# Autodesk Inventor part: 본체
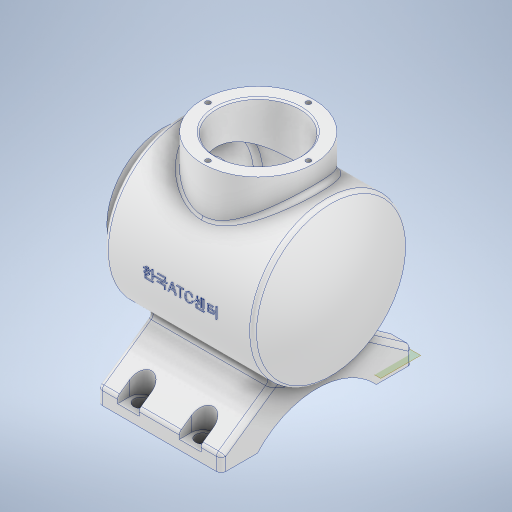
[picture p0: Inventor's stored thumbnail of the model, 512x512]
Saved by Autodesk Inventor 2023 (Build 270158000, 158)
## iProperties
Created: 2023-12
Part Number: 본체
Material: 알루미늄 6061
Document SubType Name: Modeling
Designer: asung
Mass: 1296.69 g
Surface Area: 1060.45 cm^2
Volume: 480.256 cm^3
Density: 2.7 g/cm^3
Appearance: 알루미늄 - 평지
Author: asung
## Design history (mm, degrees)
sketch "스케치1"
  geometry: L1 (60, 0)-(-60, 0); L2 (-60, 0)-(-60, 36); L3 (-60, 36)-(-48, 36); L4 (-48, 36)-(-48, 50); L5 (-48, 50)-(48.336, 50); L6 (-41, 43)-(43.887, 43); L7 (-41, 27)-(-41, 43); L8 (-60, 0)-(-60, 27); L9 (-60, 27)-(-41, 27); A1 r 113 centre (-53, 0) between (60, 0) and (48.336, 50); A2 r 106 centre (-53, 0) between (53, 0) and (43.887, 43); 2 further points
  constraints: 18 end point, 4 perpendicular, 4 point on circle, 2 centre point, 1 horizontal, 1 point on line, 1 vertical
  dimensions: "d3" = 120 distance of L1.start L1.end; "d4" = 36 distance of L1.end L2.end; "d5" = 12 distance of L2.end L3.end; "d6" = 14 distance of L3.end L4.end; "d13" = 7 distance between parallel lines of L5 L6; "d15" = 27 distance of L1.end L8.end; "d16" = 19 distance of L7.start L8.end
revolve "회전1" sketch "스케치1" stored, may be unused: angle "d17" = 360 deg
fillet "모깎기3" dims "d20" = 3
fillet "모깎기4" dims "d21" = 3
chamfer "모따기1" distance "d22" = 1; stored, may be unused: second distance "d23" = 2, angle "d24" = 45 deg
node "작업 평면1"
node "작업 평면4"
node "작업 평면5"
sketch "스케치5" dims "d47" = 65
  geometry: 3 further points
  constraints: 1 coincident, 1 vertical alignment, 2 other
hole "구멍2" sketch "스케치5" at (0, 32.5) diameter "d48" = 3.242; stored, may be unused: countersink angle "d52" = 90 deg, drill point angle "d54" = 118 deg; dims "d49" = 8, "d50" = 4, "d51" = 2, "d53" = 10
sketch "스케치6"
  geometry: L1 (0, 0)-(-77, 0); L2 (-77, 0)-(-77, 38.5); L3 (-77, 38.5)-(-77, 62); L4 (-77, 62)-(-67, 62); L5 (-67, 62)-(-42.278, 26.694); L6 (-77, 0)-(-77, -38.5); L7 (-77, -38.5)-(-77, -62); L8 (-77, -62)-(-67, -62); L9 (-67, -62)-(-42.278, -26.694); C1 r 43 at (0, 0) reference; A1 r 50 centre (0, 0) between (-42.278, 26.694) and (-42.278, -26.694) reference; A2 r 52.096 centre (-112.096, 0) between (-77, -38.5) and (-77, 38.5); 4 further points
  constraints: 18 end point, 4 point on circle, 3 perpendicular, 2 point on line, 1 centre point, 1 horizontal, 1 vertical, 2 other
  dimensions: "d58" = 77 distance of L1.start L1.end; "d59" = 38.5 distance of L1.end L2.end; "d60" = 38.5 distance of L1.end L6.end; "d61" = 10 distance of L7.end L8.end; "d62" = 17 horizontal distance of L2.end point (-60, 0); "d63" = 10 distance of L4.end L3.end; "d64" = 55 deg angle of L4 L5; "d65" = 55 deg angle of L8 L9; "d79" = 62 distance from line of L1.end L8; "d80" = 62 distance between parallel lines of L4 L1
extrude "돌출3" join sketch "스케치6" stored distance "d66" = 80; taper "d67" = 0 deg
fillet "모깎기6" dims "d68" = 3
fillet "모깎기7" dims "d69" = 3
fillet "모깎기8" dims "d70" = 3
sketch "스케치7"
  geometry: L1 (80, 97.5)-(80, 77) reference; L2 (80, 77)-(0, 77) reference; L3 (0, 77)-(0, 97.5) reference; L4 (3, 100.5)-(77, 100.5) reference; L5 (80, 0)-(80, -20.5) reference; L6 (77, -23.5)-(3, -23.5) reference; L7 (0, -20.5)-(0, 0) reference; L8 (0, 0)-(80, 0) reference; C1 r 4.5 at (20, -15.5); C2 r 4.5 at (20, 92.5); C3 r 4.5 at (60, 92.5); C4 r 4.5 at (60, -15.5); A1 r 3 centre (3, 97.5) between (3, 100.5) and (0, 97.5) reference; A2 r 3 centre (77, 97.5) between (80, 97.5) and (77, 100.5) reference; A3 r 3 centre (77, -20.5) between (77, -23.5) and (80, -20.5) reference; A4 r 3 centre (3, -20.5) between (0, -20.5) and (3, -23.5) reference; 1 further point
  constraints: 4 centre point
  dimensions: "d71" = 9 diameter of C1; "d72" = 20 distance from line of L7 C1.centre; "d76" = 20 distance from line of L3 C2.centre; "d81" = 108 distance of C2.centre C1.centre; "d82" = 8 distance from line of L4 C2.centre
extrude "돌출4" cut sketch "스케치7" stored distance "d83" = 80; taper "d84" = 0 deg
node "작업 평면2"
sketch "스케치8"
  geometry: L1 (80, 97.5)-(80, 70.517) reference; L2 (80, 70.517)-(0, 70.517) reference; L3 (0, 70.517)-(0, 97.5) reference; L4 (3, 100.5)-(77, 100.5) reference; L5 (80, 6.483)-(80, -20.5) reference; L6 (77, -23.5)-(3, -23.5) reference; L7 (0, -20.5)-(0, 6.483) reference; L8 (0, 6.483)-(80, 6.483) reference; L9 (13, 92.5)-(13, 105.537); L10 (27, 92.5)-(27, 111.612); L11 (53, 92.5)-(53, 114.449); L12 (67, 92.5)-(67, 116.315); L13 (13, -15.5)-(13, -37.217); L14 (88.336, -11.5)-(-8, -11.5) reference; L15 (27, -15.5)-(27, -37.217); L16 (53, -15.5)-(53, -36.443); L17 (67, -15.5)-(67, -42.796); C1 r 4.5 at (60, 92.5) reference; C2 r 4.5 at (20, -15.5) reference; C3 r 4.5 at (20, 92.5) reference; C4 r 4.5 at (60, -15.5) reference; C5 r 4.5 at (20, -15.5) reference; C6 r 4.5 at (60, -15.5) reference; C7 r 4.5 at (20, 92.5) reference; A1 r 3 centre (3, 97.5) between (3, 100.5) and (0, 97.5) reference; A2 r 3 centre (77, 97.5) between (80, 97.5) and (77, 100.5) reference; A3 r 3 centre (77, -20.5) between (77, -23.5) and (80, -20.5) reference; A4 r 3 centre (3, -20.5) between (0, -20.5) and (3, -23.5) reference; A5 r 7 centre (20, -15.5) between (13, -15.5) and (27, -15.5); A6 r 7 centre (60, -15.5) between (53, -15.5) and (67, -15.5); A7 r 7 centre (60, 92.5) between (53, 92.5) and (67, 92.5); A8 r 7 centre (20, 92.5) between (13, 92.5) and (27, 92.5); 9 further points
  constraints: 16 end point, 8 point on circle, 8 tangent, 6 vertical, 4 centre point, 4 coincident, 2 perpendicular
  dimensions: "d86" = 14 diameter of A5; "d87" = 14 diameter of A6; "d88" = 14 diameter of A7; "d89" = 14 diameter of A8
extrude "돌출5" cut sketch "스케치8" stored distance "d90" = 10; taper "d91" = 0 deg
node "작업 평면3"
fillet "모깎기9" dims "d92" = 3
sketch "스케치9"
  geometry: L1 (-60.168, 36)-(-60.168, -36) reference; 2 further points
  constraints: 1 horizontal alignment, 1 other
  dimensions: "d93" = 62 distance from line of L1 point (1.832, 0)
feature "엠보싱1" sketch "스케치9" dims "d3" = 120, "d4" = 36, "d5" = 12, "d6" = 14, "d13" = 7, "d15" = 27, "d16" = 19, "d94" = 0.5, "d95" = 0
sketch "스케치10"
  geometry: L1 (-60, 36)-(-60, -36) reference; C1 r 36 at (2, 0); 1 further point
  constraints: 1 centre point
  dimensions: "d96" = 72 diameter of C1; "d97" = 62 distance from line of L1 C1.centre
extrude "돌출6" join sketch "스케치10" stored distance "d98" = 10; taper "d99" = 0 deg
sketch "스케치11"
  geometry: C1 r 27 at (0, 0); 1 further point
  constraints: 1 centre point
  dimensions: "d100" = 54 diameter of C1
extrude "돌출7" cut sketch "스케치11" stored distance "d101" = 10; taper "d102" = 0 deg
fillet "모깎기10" dims "d103" = 3
chamfer "모따기3" distance "d104" = 1; stored, may be unused: second distance "d105" = 2, angle "d106" = 45 deg
sketch "스케치12" dims "d107" = 65
  geometry: 3 further points
  constraints: 1 horizontal alignment, 2 other
hole "구멍3" sketch "스케치12" at (-32.5, 0) diameter "d108" = 3.242; stored, may be unused: countersink angle "d112" = 90 deg, drill point angle "d114" = 118 deg; dims "d109" = 8, "d110" = 4, "d111" = 2, "d113" = 10
node "솔리드1"
pattern_circular "원형 패턴2" dims angle "d56" = 360 deg
pattern_circular "원형 패턴3" dims angle "d116" = 360 deg
node "절단 모서리 투영1"
node "절단 모서리 투영2"
node "절단 모서리 투영3"
feature "A9D066F2-1C7D-4E18-AEED-F7BC21143FA4" dims "d48" = 3.242, "d49" = 8, "d50" = 4, "d51" = 2, "d52" = 90 deg, "d53" = 10, "d54" = 118 deg
other parameters: "d25" = 65, "d85" = -6
